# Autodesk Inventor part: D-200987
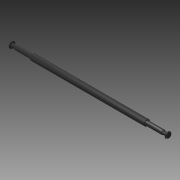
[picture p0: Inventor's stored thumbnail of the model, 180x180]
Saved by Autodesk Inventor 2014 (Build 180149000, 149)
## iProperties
Created: 2007-10
Part Number: D-200987
Document SubType Name: Modeling
Designer: TH
Density: 7.85 g/cm^3
Mass: 525.707 g
Surface Area: 188.847 cm^2
Volume: 66.969 cm^3
Material: Steel
Description: PIVOT BAR
Appearance: Rubber - Black - Version 1.1
Component Category: Lower Component
Rod_Major_Diameter: 15.000 mm
Author: TH
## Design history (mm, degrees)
sketch "Sketch1"
  geometry: L1 (200.198, 0)-(-200.198, 0); L2 (-200.198, 0)-(-200.198, 5.045); L3 (-197.323, 7.92)-(-197.25, 7.92); L4 (-197.25, 7.92)-(-197.25, 4.18); L5 (-197.25, 4.18)-(-185.65, 4.18); L6 (-185.65, 4.18)-(-185.65, 5.475); L7 (-185.65, 5.475)-(-144.5, 5.475); L8 (-144.5, 5.475)-(-144.5, 7.5); L9 (-144.5, 7.5)-(144.5, 7.5); L10 (144.5, 7.5)-(144.5, 5.475); L11 (144.5, 5.475)-(185.65, 5.475); L12 (185.65, 5.475)-(185.65, 4.18); L13 (185.65, 4.18)-(197.25, 4.18); L14 (197.25, 4.18)-(197.25, 7.92); L15 (197.25, 7.92)-(197.323, 7.92); L16 (200.198, 5.045)-(200.198, 0); A1 r 2.875 centre (-197.323, 5.045) between (-197.323, 7.92) and (-200.198, 5.045); A2 r 2.875 centre (197.323, 5.045) between (200.198, 5.045) and (197.323, 7.92); 2 further points
  constraints: 32 end point, 12 parallel, 4 point on circle, 4 tangent, 2 centre point, 2 perpendicular, 1 coincident, 1 collinear, 1 equal radius, 1 horizontal, 1 midpoint
  dimensions: "d0" = 400.396 distance of L1.start L1.end; "d2" = 15 diameter of L9 L1 (= Rod_Major_Diameter); "d3" = 10.95 diameter of L7 L1; "d4" = 8.36 diameter of L5 L1; "d5" = 15.84 diameter of L3 L1; "d6" = 10.95 diameter of L11 L1 (= d3); "d7" = 8.36 diameter of L13 L1 (= d4); "d8" = 15.84 diameter of L15 L1 (= d5); "d9" = 289 distance of L8.end L9.end; "d10" = 144.5 distance from line of L8 point (0, 0) (= 0.5 x d9); "d12" = 11.6 distance of L4.end L5.end; "d13" = 11.6 distance of L12.end L13.end (= d12); "d15" = 2.875 radius of A1; "d21" = 2.948 distance between parallel lines of L16 L14; "d22" = 2.948 distance between parallel lines of L2 L4
revolve "Revolution1" sketch "Sketch1" stored, may be unused: angle "d16" = 90 deg
feature "Surface1"
workplane "Work Plane1"
workplane "Work Plane2"
body "Solid1"
body "Srf1"
other parameters: "d23" = -10 deg, "Rod_Major_Diameter" = 15 [user parameter; used in 1 equation term], "Rod_Minor_Diameter" = 10.95 [user parameter]
